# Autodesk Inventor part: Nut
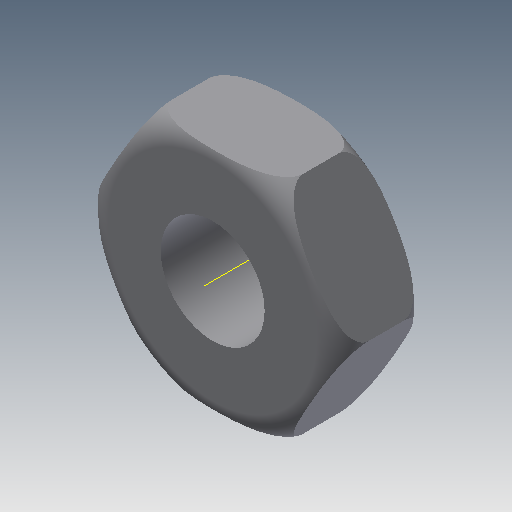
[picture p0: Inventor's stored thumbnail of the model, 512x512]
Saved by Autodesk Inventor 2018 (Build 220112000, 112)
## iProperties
Created: 2009-04
Part Number: Nut
Document SubType Name: Modeling
Designer: Sham
Density: 1 g/cm^3
Material: Generic
Appearance: Default
Mass: 4.65064 g
Surface Area: 21.3319 cm^2
Volume: 4.65064 cm^3
Author: Sham
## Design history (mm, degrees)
sketch "Sketch1"
  geometry: L1 (7.5, 12.99)-(15, 0); L2 (15, 0)-(7.5, -12.99); L3 (7.5, -12.99)-(-7.5, -12.99); L4 (-7.5, -12.99)-(-15, 0); L5 (-15, 0)-(-7.5, 12.99); L6 (-7.5, 12.99)-(7.5, 12.99); C1 r 6 at (0, 0); 1 further point
  constraints: 12 end point, 1 centre point, 1 coincident, 13 other
  dimensions: "d0" = 30 distance of L1.end L4.end; "d1" = 12 diameter of C1
extrude "Extrusion1" new body sketch "Sketch1" distance "d2" = 12; taper "d3" = 0 deg
sketch "Sketch2"
  geometry: L1 (-12, 0)-(-12, -0.022); L2 (-15, 7)-(-15, 3); L3 (0, -2.87)-(0, 12.87) reference; A1 r 3 centre (-12, 7) between (-12, 10) and (-15, 7); A2 r 3 centre (-12, 3) between (-15, 3) and (-12, 0)
  constraints: 4 end point, 4 point on circle, 2 centre point, 1 tangent
revolve "Revolution1" sketch "Sketch2" stored, may be unused: angle "d7" = 90 deg
body "Solid1"
other parameters: "d6" = 90 deg
